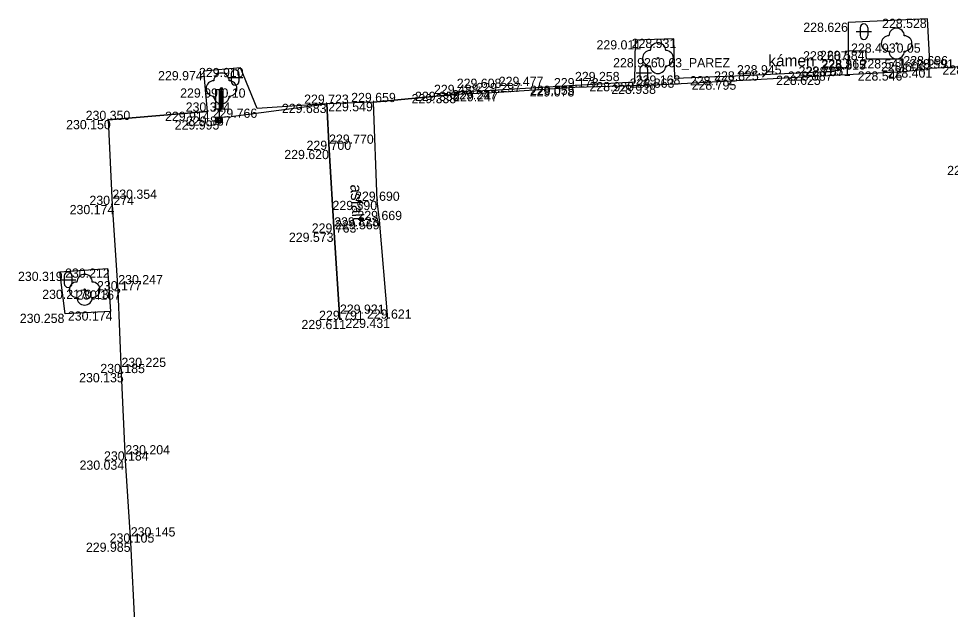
# Model space of a CAD drawing. Extents: x -599516 to -599132, y -1163668 to -1163119.
# Drawn here: x -599435.4 to -599405.11, y -1163193.09 to -1163173.87 of the extents above; entities that cross this region are included whole.
import ezdxf

# ---------------------------------------------------------------- set-up
doc = ezdxf.new("R2010")
doc.units = 0
for name, color, linetype in [('Bod-oznac1', 7, 'Continuous'), ('Bod-oznac2', 7, 'Continuous'), ('Bod-oznac3', 7, 'Continuous'), ('Bod-vyska1', 7, 'Continuous'), ('Bod-vyska2', 7, 'Continuous'), ('Bod-vyska3', 7, 'Continuous'), ('Z_cela-hrobu-dolni-linie', 7, 'Continuous'), ('Z_cela-hrobu-horni-linie', 7, 'Continuous'), ('Z_chodnik', 7, 'Continuous'), ('Z_komunikace', 7, 'Continuous'), ('Z_kultury-znacky', 7, 'Continuous'), ('Z_nove-stromy-prumer-kmene', 7, 'Continuous'), ('Z_obvod-kmene-spodek-ve-vysce1_2m', 7, 'Continuous'), ('Z_parez-stromu', 7, 'Continuous'), ('Z_popis-budov-povrchu', 7, 'Continuous'), ('Z_stromy-nove-vysazene', 7, 'Continuous'), ('Z_vol-lin-odkazova-cara', 7, 'Continuous'), ('Z_znacky-ostatni-orientacni-sloupek', 7, 'Continuous'), ('Z_zpevnene-plochy', 7, 'Continuous')]:
    doc.layers.add(name, color=color, linetype=linetype)

msp = doc.modelspace()

# ---------------------------------------------------------------- linework, layer by layer
at = {"layer": 'Bod-oznac1'}
for p, q in [((-599408.431, -1163173.996), (-599408.431, -1163173.996)), ((-599405.848, -1163173.87), (-599405.848, -1163173.87)), ((-599415.353, -1163174.569), (-599415.353, -1163174.569)), ((-599414.105, -1163174.522), (-599414.105, -1163174.522)), ((-599408.427, -1163174.927), (-599408.427, -1163174.927)), ((-599407.858, -1163174.913), (-599407.858, -1163174.913)), ((-599406.857, -1163174.675), (-599406.857, -1163174.675)), ((-599414.615, -1163175.152), (-599414.615, -1163175.152)), ((-599407.841, -1163175.186), (-599407.841, -1163175.186)), ((-599406.642, -1163175.188), (-599406.642, -1163175.188)), ((-599429.395, -1163175.573), (-599429.395, -1163175.573)), ((-599428.184, -1163175.47), (-599428.184, -1163175.47)), ((-599408.427, -1163175.436), (-599408.427, -1163175.436)), ((-599405.762, -1163175.487), (-599405.762, -1163175.487)), ((-599414.062, -1163175.816), (-599414.062, -1163175.816)), ((-599412.093, -1163175.738), (-599412.093, -1163175.738)), ((-599412.048, -1163175.88), (-599412.048, -1163175.88)), ((-599409.304, -1163175.722), (-599409.304, -1163175.722)), ((-599408.909, -1163175.586), (-599408.909, -1163175.586)), ((-599406.638, -1163175.583), (-599406.638, -1163175.583)), ((-599428.806, -1163176.137), (-599428.806, -1163176.137)), ((-599417.314, -1163176.099), (-599417.314, -1163176.099)), ((-599417.308, -1163176.047), (-599417.308, -1163176.047)), ((-599415.375, -1163175.929), (-599415.375, -1163175.929)), ((-599414.662, -1163176.015), (-599414.662, -1163176.015)), ((-599421.156, -1163176.319), (-599421.156, -1163176.319)), ((-599421.044, -1163176.243), (-599421.044, -1163176.243)), ((-599419.821, -1163176.193), (-599419.821, -1163176.193)), ((-599419.79, -1163176.258), (-599419.79, -1163176.258)), ((-599425.383, -1163176.638), (-599425.383, -1163176.638)), ((-599423.866, -1163176.582), (-599423.866, -1163176.582)), ((-599429.275, -1163176.893), (-599429.275, -1163176.893)), ((-599428.498, -1163177.05), (-599428.498, -1163177.05)), ((-599427.645, -1163176.794), (-599427.645, -1163176.794)), ((-599432.482, -1163177.164), (-599432.482, -1163177.164)), ((-599428.879, -1163177.175), (-599428.879, -1163177.175)), ((-599425.307, -1163178.138), (-599425.307, -1163178.138)), ((-599423.74, -1163179.795), (-599423.74, -1163179.795)), ((-599432.353, -1163179.929), (-599432.353, -1163179.929)), ((-599423.669, -1163180.422), (-599423.669, -1163180.422)), ((-599425.142, -1163180.83), (-599425.142, -1163180.83)), ((-599434.057, -1163182.104), (-599434.057, -1163182.104)), ((-599432.515, -1163181.997), (-599432.515, -1163181.997)), ((-599433.256, -1163182.687), (-599433.256, -1163182.687)), ((-599432.162, -1163182.708), (-599432.162, -1163182.708)), ((-599432.41, -1163183.392), (-599432.41, -1163183.392)), ((-599433.883, -1163183.469), (-599433.883, -1163183.469)), ((-599424.955, -1163183.67), (-599424.955, -1163183.67)), ((-599423.399, -1163183.63), (-599423.399, -1163183.63)), ((-599432.058, -1163185.401), (-599432.058, -1163185.401)), ((-599431.931, -1163188.246), (-599431.931, -1163188.246)), ((-599431.754, -1163190.917), (-599431.754, -1163190.917))]:
    msp.add_line(p, q, dxfattribs=at)
at = {"layer": 'Bod-oznac2'}
for p, q in [((-599405.762, -1163175.487), (-599405.762, -1163175.487)), ((-599412.048, -1163175.88), (-599412.048, -1163175.88)), ((-599409.304, -1163175.722), (-599409.304, -1163175.722)), ((-599406.638, -1163175.583), (-599406.638, -1163175.583)), ((-599417.314, -1163176.099), (-599417.314, -1163176.099)), ((-599414.662, -1163176.015), (-599414.662, -1163176.015)), ((-599421.156, -1163176.319), (-599421.156, -1163176.319)), ((-599419.79, -1163176.258), (-599419.79, -1163176.258)), ((-599425.383, -1163176.638), (-599425.383, -1163176.638)), ((-599423.866, -1163176.582), (-599423.866, -1163176.582)), ((-599429.275, -1163176.893), (-599429.275, -1163176.893)), ((-599432.482, -1163177.164), (-599432.482, -1163177.164)), ((-599425.307, -1163178.138), (-599425.307, -1163178.138)), ((-599423.74, -1163179.795), (-599423.74, -1163179.795)), ((-599432.353, -1163179.929), (-599432.353, -1163179.929)), ((-599423.669, -1163180.422), (-599423.669, -1163180.422)), ((-599425.142, -1163180.83), (-599425.142, -1163180.83)), ((-599432.162, -1163182.708), (-599432.162, -1163182.708)), ((-599424.955, -1163183.67), (-599424.955, -1163183.67)), ((-599423.399, -1163183.63), (-599423.399, -1163183.63)), ((-599432.058, -1163185.401), (-599432.058, -1163185.401)), ((-599431.931, -1163188.246), (-599431.931, -1163188.246)), ((-599431.754, -1163190.917), (-599431.754, -1163190.917))]:
    msp.add_line(p, q, dxfattribs=at)
at = {"layer": 'Bod-oznac3'}
for p, q in [((-599412.048, -1163175.88), (-599412.048, -1163175.88)), ((-599409.304, -1163175.722), (-599409.304, -1163175.722)), ((-599406.638, -1163175.583), (-599406.638, -1163175.583)), ((-599417.314, -1163176.099), (-599417.314, -1163176.099)), ((-599421.156, -1163176.319), (-599421.156, -1163176.319)), ((-599419.79, -1163176.258), (-599419.79, -1163176.258)), ((-599425.307, -1163178.138), (-599425.307, -1163178.138)), ((-599432.353, -1163179.929), (-599432.353, -1163179.929)), ((-599425.142, -1163180.83), (-599425.142, -1163180.83)), ((-599432.162, -1163182.708), (-599432.162, -1163182.708)), ((-599424.955, -1163183.67), (-599424.955, -1163183.67)), ((-599432.058, -1163185.401), (-599432.058, -1163185.401)), ((-599431.931, -1163188.246), (-599431.931, -1163188.246)), ((-599431.754, -1163190.917), (-599431.754, -1163190.917))]:
    msp.add_line(p, q, dxfattribs=at)
at = {"layer": 'Z_cela-hrobu-dolni-linie'}
msp.add_line((-599428.498, -1163177.05), (-599425.383, -1163176.638), dxfattribs=at)
msp.add_lwpolyline([(-599421.156, -1163176.319), (-599419.79, -1163176.258), (-599417.314, -1163176.099), (-599414.662, -1163176.015), (-599412.048, -1163175.88), (-599409.304, -1163175.722), (-599406.638, -1163175.583), (-599405.762, -1163175.487)], dxfattribs=at)
at = {"layer": 'Z_cela-hrobu-horni-linie'}
msp.add_line((-599423.399, -1163183.63), (-599423.669, -1163180.422), dxfattribs=at)
for points in [[(-599414.662, -1163176.015), (-599412.048, -1163175.88), (-599412.048, -1163175.88), (-599409.304, -1163175.722), (-599409.304, -1163175.722), (-599406.638, -1163175.583), (-599406.638, -1163175.583), (-599405.762, -1163175.487)], [(-599403.742, -1163178.657), (-599403.893, -1163175.387), (-599405.762, -1163175.487)], [(-599423.74, -1163179.795), (-599423.866, -1163176.582), (-599421.156, -1163176.319), (-599421.156, -1163176.319), (-599419.79, -1163176.258), (-599419.79, -1163176.258), (-599417.314, -1163176.099), (-599417.314, -1163176.099), (-599414.662, -1163176.015)], [(-599428.498, -1163177.05), (-599425.383, -1163176.638), (-599425.307, -1163178.138), (-599425.307, -1163178.138), (-599425.142, -1163180.83), (-599425.142, -1163180.83), (-599424.955, -1163183.67), (-599424.955, -1163183.67)], [(-599431.199, -1163201.76), (-599431.341, -1163199.08), (-599431.341, -1163199.08), (-599431.456, -1163196.487), (-599431.456, -1163196.487), (-599431.611, -1163193.713), (-599431.611, -1163193.713), (-599431.754, -1163190.917), (-599431.754, -1163190.917), (-599431.931, -1163188.246), (-599431.931, -1163188.246), (-599432.058, -1163185.401), (-599432.058, -1163185.401), (-599432.162, -1163182.708), (-599432.162, -1163182.708), (-599432.353, -1163179.929), (-599432.353, -1163179.929), (-599432.482, -1163177.164), (-599429.275, -1163176.893)]]:
    msp.add_lwpolyline(points, dxfattribs=at)
at = {"layer": 'Z_chodnik'}
for points in [[(-599424.955, -1163183.67), (-599425.142, -1163180.83), (-599425.307, -1163178.138), (-599425.383, -1163176.638)], [(-599423.399, -1163183.63), (-599423.669, -1163180.422), (-599423.74, -1163179.795), (-599423.866, -1163176.582)]]:
    msp.add_lwpolyline(points, dxfattribs=at)
at = {"layer": 'Z_komunikace'}
for points in [[(-599405.762, -1163175.487), (-599405.848, -1163173.87), (-599408.431, -1163173.996), (-599408.427, -1163174.927), (-599408.427, -1163175.436), (-599408.909, -1163175.586), (-599412.093, -1163175.738), (-599414.062, -1163175.816), (-599414.105, -1163174.522), (-599415.353, -1163174.569), (-599415.375, -1163175.929), (-599417.308, -1163176.047), (-599419.821, -1163176.193), (-599421.044, -1163176.243), (-599421.156, -1163176.319), (-599423.866, -1163176.582), (-599425.383, -1163176.638), (-599427.645, -1163176.794), (-599428.184, -1163175.47), (-599429.395, -1163175.573), (-599429.275, -1163176.893), (-599432.482, -1163177.164)], [(-599403.893, -1163175.387), (-599405.762, -1163175.487)], [(-599430.927, -1163206.18), (-599430.978, -1163205.148), (-599431.029, -1163204.335), (-599431.107, -1163203.365), (-599431.199, -1163201.76), (-599431.219, -1163201.395), (-599433.053, -1163201.555), (-599433.222, -1163199.723), (-599431.317, -1163199.535), (-599431.341, -1163199.08), (-599431.456, -1163196.487), (-599431.611, -1163193.713), (-599431.754, -1163190.917), (-599431.931, -1163188.246), (-599432.058, -1163185.401), (-599432.162, -1163182.708), (-599432.353, -1163179.929), (-599432.482, -1163177.164)], [(-599433.883, -1163183.469), (-599434.057, -1163182.104), (-599432.515, -1163181.997), (-599432.41, -1163183.392), (-599433.883, -1163183.469)]]:
    msp.add_lwpolyline(points, dxfattribs=at)
at = {"layer": 'Z_kultury-znacky'}
for p, q in [((-599408.17, -1163174.29), (-599407.67, -1163174.29)), ((-599408.045, -1163174.165), (-599408.045, -1163174.415)), ((-599407.795, -1163174.165), (-599407.795, -1163174.415)), ((-599415.201, -1163175.51), (-599415.201, -1163175.76)), ((-599414.951, -1163175.51), (-599414.951, -1163175.76)), ((-599428.612, -1163175.784), (-599428.112, -1163175.784)), ((-599428.487, -1163175.659), (-599428.487, -1163175.909)), ((-599428.237, -1163175.659), (-599428.237, -1163175.909)), ((-599415.326, -1163175.635), (-599414.826, -1163175.635)), ((-599433.917, -1163182.236), (-599433.917, -1163182.486)), ((-599433.667, -1163182.236), (-599433.667, -1163182.486)), ((-599434.042, -1163182.361), (-599433.542, -1163182.361))]:
    msp.add_line(p, q, dxfattribs=at)
for centre, start, end in [((-599407.92, -1163174.165), 0, 180), ((-599407.92, -1163174.415), 180, 0), ((-599428.362, -1163175.66), 0, 180), ((-599415.076, -1163175.51), 0, 180), ((-599415.076, -1163175.76), 180, 0), ((-599428.362, -1163175.91), 180, 0), ((-599433.792, -1163182.236), 0, 180), ((-599433.792, -1163182.486), 180, 0)]:
    msp.add_arc(centre, 0.125, start, end, dxfattribs=at)
at = {"layer": 'Z_parez-stromu'}
msp.add_circle((-599414.615, -1163175.152), 0.025, dxfattribs=at)
for centre, start, end in [((-599414.615, -1163174.902), 0, 180), ((-599414.865, -1163175.152), 90, 270), ((-599414.365, -1163175.152), 270, 90), ((-599414.615, -1163175.402), 180, 0)]:
    msp.add_arc(centre, 0.25, start, end, dxfattribs=at)
at = {"layer": 'Z_stromy-nove-vysazene'}
for centre in [(-599406.857, -1163174.675), (-599428.806, -1163176.137), (-599433.256, -1163182.687)]:
    msp.add_circle(centre, 0.025, dxfattribs=at)
for centre, start, end in [((-599406.857, -1163174.425), 0, 180), ((-599407.107, -1163174.675), 90, 270), ((-599406.607, -1163174.675), 270, 90), ((-599406.857, -1163174.925), 180, 0), ((-599428.806, -1163175.887), 0, 180), ((-599429.056, -1163176.137), 90, 270), ((-599428.556, -1163176.137), 270, 90), ((-599428.806, -1163176.387), 180, 0), ((-599433.256, -1163182.437), 0, 180), ((-599433.506, -1163182.687), 90, 270), ((-599433.006, -1163182.687), 270, 90), ((-599433.256, -1163182.937), 180, 0)]:
    msp.add_arc(centre, 0.25, start, end, dxfattribs=at)
at = {"layer": 'Z_vol-lin-odkazova-cara'}
msp.add_line((-599411.212, -1163175.766), (-599410.981, -1163175.523), dxfattribs=at)
at = {"layer": 'Z_znacky-ostatni-orientacni-sloupek'}
for p, q in [((-599429.004, -1163176.175), (-599429.004, -1163176.8)), ((-599429.004, -1163176.175), (-599428.879, -1163176.175)), ((-599429.004, -1163176.8), (-599428.879, -1163176.8)), ((-599428.879, -1163176.8), (-599428.879, -1163177.075))]:
    msp.add_line(p, q, dxfattribs=at)
for points in [[(-599428.879, -1163176.8), (-599428.754, -1163176.8), (-599428.754, -1163176.175), (-599428.879, -1163176.175)], [(-599428.836, -1163176.758), (-599428.797, -1163176.758), (-599428.797, -1163176.218), (-599428.836, -1163176.218)]]:
    msp.add_lwpolyline(points, close=True, dxfattribs=at)
for radius in [0.1, 0.065, 0.03]:
    msp.add_circle((-599428.879, -1163177.175), radius, dxfattribs=at)
at = {"layer": 'Z_zpevnene-plochy'}
msp.add_lwpolyline([(-599406.638, -1163175.583), (-599406.642, -1163175.188), (-599407.841, -1163175.186), (-599407.858, -1163174.913), (-599408.427, -1163174.927)], dxfattribs=at)

# ---------------------------------------------------------------- texts
at = {"layer": 'Bod-vyska1'}
for s, p in [('228.626', (-599409.89, -1163174.296)), ('228.528', (-599407.33, -1163174.17)), ('229.011', (-599416.613, -1163174.869)), ('228.931', (-599415.471, -1163174.822)), ('228.493', (-599408.338, -1163174.975)), ('228.607', (-599409.897, -1163175.227)), ('228.584', (-599409.351, -1163175.213)), ('228.926', (-599416.074, -1163175.452)), ('228.569', (-599409.3, -1163175.486)), ('228.541', (-599408.031, -1163175.488)), ('229.974', (-599430.867, -1163175.873)), ('229.910', (-599429.537, -1163175.77)), ('228.571', (-599409.806, -1163175.736)), ('228.546', (-599408.12, -1163175.883)), ('228.401', (-599407.149, -1163175.787)), ('228.267', (-599405.365, -1163175.687)), ('228.863', (-599415.532, -1163176.116)), ('228.772', (-599413.578, -1163176.038)), ('228.795', (-599413.52, -1163176.18)), ('228.625', (-599410.774, -1163176.022)), ('228.587', (-599410.392, -1163175.886)), ('229.991', (-599430.149, -1163176.437)), ('229.078', (-599418.784, -1163176.399)), ('229.055', (-599418.776, -1163176.347)), ('228.920', (-599416.843, -1163176.229)), ('228.938', (-599416.132, -1163176.315)), ('229.338', (-599422.626, -1163176.619)), ('229.355', (-599422.514, -1163176.543)), ('229.247', (-599421.304, -1163176.493)), ('229.247', (-599421.273, -1163176.558)), ('229.766', (-599429.094, -1163177.094)), ('229.683', (-599426.842, -1163176.938)), ('229.549', (-599425.336, -1163176.882)), ('229.914', (-599430.641, -1163177.193)), ('229.867', (-599429.959, -1163177.35)), ('230.150', (-599433.856, -1163177.464)), ('229.995', (-599430.326, -1163177.475)), ('229.620', (-599426.764, -1163178.438)), ('228.279', (-599405.214, -1163178.957)), ('229.590', (-599425.197, -1163180.095)), ('230.174', (-599433.742, -1163180.229)), ('229.569', (-599425.116, -1163180.722)), ('229.573', (-599426.614, -1163181.13)), ('230.319', (-599435.421, -1163182.404)), ('230.212', (-599433.891, -1163182.297)), ('230.217', (-599434.634, -1163182.987)), ('230.167', (-599433.528, -1163183.008)), ('230.174', (-599433.799, -1163183.692)), ('230.258', (-599435.363, -1163183.769)), ('229.611', (-599426.206, -1163183.97)), ('229.431', (-599424.777, -1163183.93)), ('230.135', (-599433.434, -1163185.701)), ('230.034', (-599433.42, -1163188.546)), ('229.985', (-599433.213, -1163191.217))]:
    msp.add_text(s, height=0.3, dxfattribs=at).set_placement(p)
at = {"layer": 'Bod-vyska2'}
for s, p in [('228.591', (-599406.445, -1163175.487)), ('228.825', (-599412.789, -1163175.88)), ('228.705', (-599410.045, -1163175.722)), ('228.606', (-599407.366, -1163175.583)), ('229.178', (-599417.998, -1163176.099)), ('229.168', (-599415.339, -1163176.015)), ('229.488', (-599421.897, -1163176.319)), ('229.297', (-599420.52, -1163176.258)), ('229.723', (-599426.119, -1163176.638)), ('229.659', (-599424.59, -1163176.582)), ('230.314', (-599429.969, -1163176.893)), ('230.350', (-599433.221, -1163177.164)), ('229.700', (-599426.041, -1163178.138)), ('229.690', (-599424.463, -1163179.795)), ('230.274', (-599433.099, -1163179.929)), ('229.669', (-599424.387, -1163180.422)), ('229.763', (-599425.872, -1163180.83)), ('230.177', (-599432.852, -1163182.708)), ('229.791', (-599425.633, -1163183.67)), ('229.621', (-599424.076, -1163183.63)), ('230.185', (-599432.746, -1163185.401)), ('230.184', (-599432.625, -1163188.246)), ('230.105', (-599432.441, -1163190.917))]:
    msp.add_text(s, height=0.3, dxfattribs=at).set_placement(p)
at = {"layer": 'Bod-vyska3'}
for s, p in [('228.815', (-599409.304, -1163175.522)), ('228.696', (-599406.638, -1163175.383)), ('228.945', (-599412.048, -1163175.68)), ('229.608', (-599421.156, -1163176.119)), ('229.477', (-599419.79, -1163176.058)), ('229.258', (-599417.314, -1163175.899)), ('229.770', (-599425.307, -1163177.938)), ('230.354', (-599432.353, -1163179.729)), ('229.823', (-599425.142, -1163180.63)), ('230.247', (-599432.162, -1163182.508)), ('229.921', (-599424.955, -1163183.47)), ('230.225', (-599432.058, -1163185.201)), ('230.204', (-599431.931, -1163188.046)), ('230.145', (-599431.754, -1163190.717))]:
    msp.add_text(s, height=0.3, dxfattribs=at).set_placement(p)
at = {"layer": 'Z_nove-stromy-prumer-kmene'}
for s, p in [('0.05', (-599406.857, -1163174.975)), ('0.10', (-599428.806, -1163176.437)), ('0.13', (-599433.256, -1163182.987))]:
    msp.add_text(s, height=0.3, dxfattribs=at).set_placement(p)
at = {"layer": 'Z_obvod-kmene-spodek-ve-vysce1_2m'}
msp.add_text('0.63_PAREZ', height=0.3, dxfattribs=at).set_placement((-599414.615, -1163175.452))
at = {"layer": 'Z_popis-budov-povrchu'}
msp.add_text('kámen', height=0.375, dxfattribs=at).set_placement((-599411.028, -1163175.419))
msp.add_text('asfalt', height=0.375, rotation=273.4503, dxfattribs=at).set_placement((-599424.621, -1163179.267))

doc.saveas('drawing.dxf')
